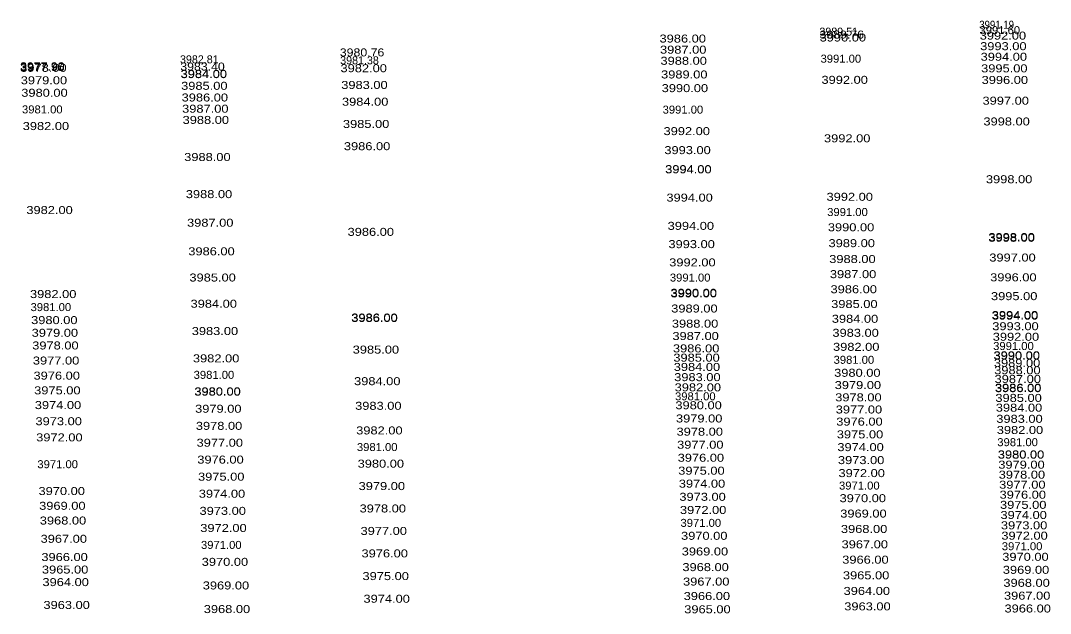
# Model space of a CAD drawing. Extents: x 49942 to 56479, y 47140 to 53283.
# Drawn here: x 52671 to 53314, y 49925 to 50296 of the extents above; entities that cross this region are included whole.
import ezdxf

# ---------------------------------------------------------------- set-up
doc = ezdxf.new("R2010")
doc.units = 0
doc.header["$LTSCALE"] = 2
doc.layers.add('29', color=7, linetype='Continuous')

msp = doc.modelspace()

# ---------------------------------------------------------------- texts
at = {"layer": '29'}
for s, width, p in [('3991.19', 0.9, (53269.905, 50290.497)), ('3986.00', 1.2, (53070.092, 50281.846)), ('3989.76', 1.15, (53170.078, 50284.336)), ('3990.00', 1.2, (53170.158, 50282.5)), ('3991.60', 1.05, (53270.052, 50287.097)), ('3992.00', 1.2, (53270.2, 50283.696)), ('3993.00', 1.2, (53270.486, 50277.092)), ('3980.76', 1.15, (52870.28, 50273.195)), ('3987.00', 1.2, (53070.393, 50274.908)), ('3991.00', 1.05, (53170.73, 50269.28)), ('3994.00', 1.2, (53270.772, 50270.487)), ('3977.90', 1.15, (52670.467, 50264.543)), ('3977.95', 1.15, (52670.488, 50264.056)), ('3978.00', 1.2, (52670.509, 50263.569)), ('3983.40', 1.15, (52770.569, 50264.348)), ('3982.00', 1.2, (52870.707, 50263.317)), ('3988.00', 1.2, (53070.693, 50267.971)), ('3995.00', 1.2, (53271.086, 50263.237)), ('3984.00', 1.2, (52770.765, 50259.827)), ('3984.00', 1.2, (52770.768, 50259.752)), ('3984.00', 1.2, (52770.773, 50259.639)), ('3989.00', 1.2, (53071.063, 50259.422)), ('3992.00', 1.2, (53171.303, 50256.059)), ('3996.00', 1.2, (53271.399, 50255.987)), ('3979.00', 1.2, (52670.846, 50255.776)), ('3985.00', 1.2, (52771.089, 50252.331)), ('3983.00', 1.2, (52871.16, 50252.855)), ('3990.00', 1.2, (53071.433, 50250.874)), ('3980.00', 1.2, (52671.184, 50247.984)), ('3986.00', 1.2, (52771.406, 50245.022)), ('3997.00', 1.2, (53271.961, 50243.021)), ('3981.00', 1.05, (52671.634, 50237.58)), ('3987.00', 1.2, (52771.709, 50238.017)), ('3984.00', 1.2, (52871.613, 50242.393)), ('3991.00', 1.05, (53072.015, 50237.445)), ('3988.00', 1.2, (52772.013, 50231.004)), ('3998.00', 1.2, (53272.522, 50230.055)), ('3982.00', 1.2, (52672.085, 50227.176)), ('3985.00', 1.2, (52872.215, 50228.495)), ('3992.00', 1.2, (53072.596, 50224.016)), ('3992.00', 1.2, (53172.884, 50219.523)), ('3986.00', 1.2, (52872.817, 50214.596)), ('3993.00', 1.2, (53073.11, 50212.143)), ('3988.00', 1.2, (52773.016, 50207.827)), ('3994.00', 1.2, (53073.624, 50200.27)), ('3994.00', 1.2, (53073.627, 50200.214)), ('3994.00', 1.2, (53073.631, 50200.116)), ('3998.00', 1.2, (53274.085, 50193.951)), ('3988.00', 1.2, (52774.02, 50184.649)), ('3994.00', 1.2, (53074.395, 50182.467)), ('3992.00', 1.2, (53174.466, 50182.988)), ('3982.00', 1.2, (52674.357, 50174.69)), ('3991.00', 1.05, (53174.879, 50173.46)), ('3987.00', 1.2, (52774.793, 50166.781)), ('3986.00', 1.2, (52875.134, 50161.07)), ('3994.00', 1.2, (53075.159, 50164.816)), ('3990.00', 1.2, (53175.291, 50163.933)), ('3993.00', 1.2, (53075.654, 50153.402)), ('3989.00', 1.2, (53175.721, 50154.009)), ('3998.00', 1.2, (53275.65, 50157.825)), ('3998.00', 1.2, (53275.659, 50157.603)), ('3998.00', 1.2, (53275.669, 50157.38)), ('3986.00', 1.2, (52775.567, 50148.914)), ('3992.00', 1.2, (53076.148, 50141.987)), ('3988.00', 1.2, (53176.151, 50144.085)), ('3997.00', 1.2, (53276.204, 50145.022)), ('3987.00', 1.2, (53176.559, 50134.649)), ('3985.00', 1.2, (52776.276, 50132.538)), ('3991.00', 1.05, (53076.559, 50132.501)), ('3996.00', 1.2, (53276.739, 50132.665)), ('3982.00', 1.2, (52676.63, 50122.203)), ('3990.00', 1.2, (53076.969, 50123.015)), ('3990.00', 1.2, (53076.972, 50122.941)), ('3990.00', 1.2, (53076.976, 50122.868)), ('3990.00', 1.2, (53076.981, 50122.74)), ('3990.00', 1.2, (53076.987, 50122.613)), ('3986.00', 1.2, (53176.968, 50125.214)), ('3995.00', 1.2, (53277.249, 50120.892)), ('3984.00', 1.2, (52776.985, 50116.163)), ('3985.00', 1.2, (53177.367, 50115.984)), ('3981.00', 1.05, (52676.982, 50114.066)), ('3989.00', 1.2, (53077.396, 50113.169)), ('3994.00', 1.2, (53277.758, 50109.119)), ('3994.00', 1.2, (53277.768, 50108.907)), ('3994.00', 1.2, (53277.777, 50108.695)), ('3980.00', 1.2, (52677.334, 50105.929)), ('3986.00', 1.2, (52877.452, 50107.54)), ('3986.00', 1.2, (52877.458, 50107.391)), ('3986.00', 1.2, (52877.465, 50107.241)), ('3988.00', 1.2, (53077.804, 50103.725)), ('3984.00', 1.2, (53177.767, 50106.755)), ('3993.00', 1.2, (53278.062, 50102.109)), ('3979.00', 1.2, (52677.677, 50098.006)), ('3983.00', 1.2, (52777.724, 50099.09)), ('3987.00', 1.2, (53078.14, 50095.985)), ('3983.00', 1.2, (53178.146, 50097.992)), ('3992.00', 1.2, (53278.347, 50095.524)), ('3978.00', 1.2, (52678.02, 50090.083)), ('3982.00', 1.2, (53178.526, 50089.229)), ('3991.00', 1.05, (53278.597, 50089.74)), ('3982.00', 1.2, (52778.463, 50082.017)), ('3985.00', 1.2, (52878.319, 50087.506)), ('3986.00', 1.2, (53078.475, 50088.245)), ('3985.00', 1.2, (53078.725, 50082.455)), ('3990.00', 1.2, (53278.848, 50083.956)), ('3990.00', 1.2, (53278.853, 50083.839)), ('3990.00', 1.2, (53278.859, 50083.705)), ('3977.00', 1.2, (52678.428, 50080.66)), ('3984.00', 1.2, (53078.976, 50076.666)), ('3981.00', 1.05, (53178.877, 50081.119)), ('3989.00', 1.2, (53279.056, 50079.139)), ('3976.00', 1.2, (52678.836, 50071.237)), ('3981.00', 1.05, (52778.909, 50071.726)), ('3983.00', 1.2, (53079.252, 50070.287)), ('3980.00', 1.2, (53179.228, 50073.008)), ('3988.00', 1.2, (53279.254, 50074.572)), ('3987.00', 1.2, (53279.489, 50069.141)), ('3984.00', 1.2, (52879.174, 50067.771)), ('3982.00', 1.2, (53079.528, 50063.908)), ('3979.00', 1.2, (53179.56, 50065.335)), ('3986.00', 1.2, (53279.724, 50063.707)), ('3986.00', 1.2, (53279.731, 50063.561)), ('3986.00', 1.2, (53279.737, 50063.414)), ('3975.00', 1.2, (52679.235, 50062.036)), ('3980.00', 1.2, (52779.356, 50061.407)), ('3980.00', 1.2, (52779.36, 50061.311)), ('3980.00', 1.2, (52779.364, 50061.214)), ('3981.00', 1.05, (53079.77, 50058.318)), ('3978.00', 1.2, (53179.893, 50057.663)), ('3985.00', 1.2, (53280.001, 50057.318)), ('3974.00', 1.2, (52679.633, 50052.834)), ('3979.00', 1.2, (52779.826, 50050.539)), ('3983.00', 1.2, (52879.84, 50052.384)), ('3980.00', 1.2, (53080.012, 50052.728)), ('3977.00', 1.2, (53180.221, 50050.083)), ('3984.00', 1.2, (53280.265, 50051.222)), ('3979.00', 1.2, (53080.37, 50044.471)), ('3983.00', 1.2, (53280.567, 50044.253)), ('3973.00', 1.2, (52680.07, 50042.743)), ('3978.00', 1.2, (52780.288, 50039.863)), ('3982.00', 1.2, (52880.506, 50036.997)), ('3976.00', 1.2, (53180.549, 50042.503)), ('3982.00', 1.2, (53280.869, 50037.285)), ('3972.00', 1.2, (52680.507, 50032.651)), ('3978.00', 1.2, (53080.728, 50036.214)), ('3975.00', 1.2, (53180.894, 50034.535)), ('3977.00', 1.2, (52780.745, 50029.312)), ('3981.00', 1.05, (52880.956, 50026.61)), ('3977.00', 1.2, (53081.08, 50028.072)), ('3974.00', 1.2, (53181.239, 50026.567)), ('3981.00', 1.05, (53281.199, 50029.649)), ('3976.00', 1.2, (52781.202, 50018.761)), ('3976.00', 1.2, (53081.433, 50019.93)), ('3973.00', 1.2, (53181.59, 50018.451)), ('3980.00', 1.2, (53281.53, 50022.014)), ('3980.00', 1.2, (53281.533, 50021.942)), ('3980.00', 1.2, (53281.536, 50021.861)), ('3971.00', 1.05, (52681.233, 50015.886)), ('3980.00', 1.2, (52881.406, 50016.224)), ('3975.00', 1.2, (53081.783, 50011.837)), ('3979.00', 1.2, (53281.807, 50015.612)), ('3975.00', 1.2, (52781.664, 50008.104)), ('3972.00', 1.2, (53181.942, 50010.335)), ('3978.00', 1.2, (53282.077, 50009.362)), ('3970.00', 1.2, (52681.959, 49999.12)), ('3979.00', 1.2, (52882.012, 50002.23)), ('3974.00', 1.2, (53082.133, 50003.744)), ('3971.00', 1.05, (53182.28, 50002.529)), ('3977.00', 1.2, (53282.349, 50003.102)), ('3974.00', 1.2, (52782.125, 49997.446)), ('3973.00', 1.2, (53082.489, 49995.521)), ('3970.00', 1.2, (53182.62, 49994.663)), ('3976.00', 1.2, (53282.62, 49996.841)), ('3969.00', 1.2, (52682.358, 49989.908)), ('3973.00', 1.2, (52782.588, 49986.741)), ('3978.00', 1.2, (52882.617, 49988.236)), ('3972.00', 1.2, (53082.845, 49987.297)), ('3975.00', 1.2, (53282.894, 49990.502)), ('3968.00', 1.2, (52682.756, 49980.696)), ('3971.00', 1.05, (53083.195, 49979.227)), ('3969.00', 1.2, (53183.037, 49985.045)), ('3974.00', 1.2, (53283.169, 49984.162)), ('3972.00', 1.2, (52783.052, 49976.035)), ('3977.00', 1.2, (52883.225, 49974.194)), ('3968.00', 1.2, (53183.453, 49975.427)), ('3973.00', 1.2, (53283.448, 49977.702)), ('3967.00', 1.2, (52683.25, 49969.294)), ('3970.00', 1.2, (53083.544, 49971.156)), ('3972.00', 1.2, (53283.728, 49971.242)), ('3971.00', 1.05, (52783.51, 49965.46)), ('3976.00', 1.2, (52883.833, 49960.153)), ('3969.00', 1.2, (53083.968, 49961.374)), ('3967.00', 1.2, (53183.868, 49965.835)), ('3971.00', 1.05, (53284.014, 49964.638)), ('3966.00', 1.2, (52683.744, 49957.891)), ('3970.00', 1.2, (52783.968, 49954.886)), ('3966.00', 1.2, (53184.284, 49956.243)), ('3970.00', 1.2, (53284.3, 49958.035)), ('3965.00', 1.2, (52684.083, 49950.058)), ('3968.00', 1.2, (53084.391, 49951.591)), ('3969.00', 1.2, (53284.652, 49949.905)), ('3964.00', 1.2, (52684.422, 49942.226)), ('3975.00', 1.2, (52884.446, 49945.989)), ('3967.00', 1.2, (53084.783, 49942.555)), ('3965.00', 1.2, (53184.707, 49946.473)), ('3968.00', 1.2, (53285.004, 49941.776)), ('3969.00', 1.2, (52784.607, 49940.129)), ('3964.00', 1.2, (53185.13, 49936.703)), ('3963.00', 1.2, (52685.04, 49927.944)), ('3974.00', 1.2, (52885.06, 49931.825)), ('3966.00', 1.2, (53085.174, 49933.518)), ('3967.00', 1.2, (53285.351, 49933.756)), ('3968.00', 1.2, (52785.245, 49925.373)), ('3965.00', 1.2, (53085.532, 49925.24)), ('3963.00', 1.2, (53185.547, 49927.057)), ('3966.00', 1.2, (53285.698, 49925.736))]:
    msp.add_text(s, height=5, dxfattribs=dict(at, width=width)).set_placement(p)
for s, p in [('3989.51', (53169.999, 50286.172)), ('3982.81', (52770.373, 50268.869)), ('3981.38', (52870.493, 50268.256))]:
    msp.add_text(s, height=5, dxfattribs=at).set_placement(p)

doc.saveas('drawing.dxf')
